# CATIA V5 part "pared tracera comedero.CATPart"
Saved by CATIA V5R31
Part number: pared tracera comedero
Bounding box of the stored display mesh (mm): x -124.2 to 124.2, y -170.5 to 29.5, z 0 to 3.3
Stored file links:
  C:\Users\189361\Desktop\pared tracera comedero.CATPart
  C:\Users\189361\Desktop\pared frontal comedero.CATPart
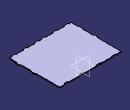
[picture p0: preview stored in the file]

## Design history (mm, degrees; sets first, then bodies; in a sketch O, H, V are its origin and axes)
Set1 "sketch"
  Sketch1 on xy-plane, origin (0, 0, 0), H (1, 0, 0), V (0, 1, 0)
    point P1 (0, 29.5)
    line L1 (0, 29.5) -> (-120.9, 29.5)
    point P2 (-120.9, 29.5)
    line L2 (-120.9, 29.5) -> (-120.9, -64.3)
    point P3 (-120.9, -167.2)
    point P4 (-95.65, -170.5)
    line L3 (-95.65, -170.5) -> (-95.65, -167.2)
    point P5 (-95.65, -167.2)
    line L4 (-95.65, -167.2) -> (-66.45, -167.2)
    point P6 (-66.45, -167.2)
    line L5 (-66.45, -167.2) -> (-66.45, -170.5)
    point P7 (-66.45, -170.5)
    line L6 (-66.45, -170.5) -> (-50.65, -170.5)
    point P8 (-50.65, -170.5)
    line L7 (-50.65, -170.5) -> (-50.65, -167.2)
    point P9 (-50.65, -167.2)
    line L8 (-50.65, -167.2) -> (-21.45, -167.2)
    point P10 (-21.45, -167.2)
    line L9 (-21.45, -167.2) -> (-21.45, -170.5)
    point P11 (-21.45, -170.5)
    line L10 (-21.45, -170.5) -> (-5.65, -170.5)
    point P12 (-5.65, -170.5)
    line L11 (-5.65, -170.5) -> (-5.65, -167.2)
    point P13 (-5.65, -167.2)
    line L12 (-5.65, -167.2) -> (0, -167.2)
    point P14 (0, -167.2)
    line L13 (-120.9, -167.2) -> (-111.45, -167.2)
    point P15 (-111.45, -167.2)
    line L14 (-111.45, -167.2) -> (-111.45, -170.5)
    point P16 (-111.45, -170.5)
    line L15 (-111.45, -170.5) -> (-95.65, -170.5)
    point P17 (-124.2, -140.1)
    line L16 (-124.2, -140.1) -> (-124.2, -124.3)
    point P18 (-124.2, -124.3)
    line L17 (-124.2, -124.3) -> (-120.9, -124.3)
    point P19 (-120.9, -124.3)
    line L18 (-124.2, -140.1) -> (-120.9, -140.1)
    point P20 (-120.9, -140.1)
    line L19 (-120.9, -140.1) -> (-120.9, -167.2)
    construction line L20 (-137.9355, -132.2) -> (-107.3097, -132.2)
    point P22 (-107.3097, -132.2)
    point P23 (120.9, 29.5)
    point P24 (120.9, -167.2)
    point P25 (95.65, -170.5)
    point P26 (95.65, -167.2)
    point P27 (66.45, -167.2)
    point P28 (66.45, -170.5)
    point P29 (50.65, -170.5)
    point P30 (50.65, -167.2)
    point P31 (21.45, -167.2)
    point P32 (21.45, -170.5)
    point P33 (5.65, -170.5)
    point P34 (5.65, -167.2)
    point P35 (111.45, -167.2)
    point P36 (111.45, -170.5)
    point P37 (124.2, -140.1)
    point P38 (124.2, -124.3)
    point P39 (120.9, -124.3)
    point P40 (120.9, -140.1)
    point P41 (107.3097, -132.2)
    line L21 (120.9, 29.5) -> (120.9, -64.3)
    line L22 (95.65, -170.5) -> (95.65, -167.2)
    line L23 (95.65, -167.2) -> (66.45, -167.2)
    line L24 (66.45, -167.2) -> (66.45, -170.5)
    line L25 (66.45, -170.5) -> (50.65, -170.5)
    line L26 (50.65, -170.5) -> (50.65, -167.2)
    line L27 (50.65, -167.2) -> (21.45, -167.2)
    line L28 (21.45, -167.2) -> (21.45, -170.5)
    line L29 (21.45, -170.5) -> (5.65, -170.5)
    line L30 (5.65, -170.5) -> (5.65, -167.2)
    line L31 (120.9, -167.2) -> (111.45, -167.2)
    line L32 (111.45, -167.2) -> (111.45, -170.5)
    line L33 (111.45, -170.5) -> (95.65, -170.5)
    line L34 (124.2, -140.1) -> (124.2, -124.3)
    line L35 (124.2, -124.3) -> (120.9, -124.3)
    line L36 (124.2, -140.1) -> (120.9, -140.1)
    line L37 (120.9, -140.1) -> (120.9, -167.2)
    point P42 (0, -167.2)
    line L38 (5.65, -167.2) -> (0, -167.2)
    point P43 (0, 29.5)
    line L39 (0, 29.5) -> (120.9, 29.5)
    construction line L40 (0, -9.1884) -> (-6.05, -9.1884)
    point P44 (0, -9.1884)
    point P45 (-6.05, -9.1884)
    construction line L41 (-6.05, -9.1884) -> (-21.05, -9.1884)
    point P46 (-21.05, -9.1884)
    construction line L42 (-21.05, -9.1884) -> (-51.05, -9.1884)
    construction line L43 (-51.05, -9.1884) -> (-66.05, -9.1884)
    point P48 (-66.05, -9.1884)
    construction line L44 (-66.05, -9.1884) -> (-96.05, -9.1884)
    construction line L45 (-96.05, -9.1884) -> (-111.05, -9.1884)
    point P50 (-111.05, -9.1884)
    axis line L46 (-142.1875, -102.2) -> (-83.2579, -102.2)
    point P53 (-120.9, -64.3)
    point P54 (-124.2, -64.3)
    line L47 (-124.2, -64.3) -> (-120.9, -64.3)
    point P55 (-124.2, -80.1)
    line L48 (-124.2, -64.3) -> (-124.2, -80.1)
    point P56 (-120.9, -80.1)
    line L49 (-124.2, -80.1) -> (-120.9, -80.1)
    line L50 (-120.9, -80.1) -> (-120.9, -124.3)
    point P57 (120.9, -64.3)
    point P58 (124.2, -64.3)
    point P59 (124.2, -80.1)
    point P60 (120.9, -80.1)
    line L51 (124.2, -64.3) -> (120.9, -64.3)
    line L52 (124.2, -64.3) -> (124.2, -80.1)
    line L53 (124.2, -80.1) -> (120.9, -80.1)
    line L54 (120.9, -80.1) -> (120.9, -124.3)
    length L4 = 29.2
    length L3 = 3.3
    distance V L2 = 120.9
    distance H L1 = 29.5
    distance P2 P3 = 196.7
    length L17 = 3.3
    distance L20 L13 = 35
    distance L20 L17 = 7.9
    distance L20 L18 = 7.9
    length L8 = 29.2
    length L40 = 6.05
    length L41 = 15
    length L42 = 30
    length L43 = 15
    length L44 = 30
    length L45 = 15
    distance P45 L11 = 0.4
    distance L9 P46 = 0.4
    distance L5 P48 = 0.4
    distance L14 P50 = 0.4
    distance L11 V = 5.65 (reference)
    distance L20 L46 = 30
    horizontal: L1 H, L4 H, L6 H, L8 H, L10 H, L12 H, L13 H, L15 H, L17 H, L18 H, L20 H, L40 H, L41 H, L42 H, L43 H, L44 H, L45 H, L46 H
    vertical: L2 V, L3 V, L5 V, L7 V, L9 V, L11 V, L14 V, L16 V, L19 V, L50 V
    coincidence: P9 L4, P13 L4, P14 V, P1 V, P3 L4, P16 L6, P20 L2, L2 L19, P1 P43, P14 P42, P44 V, L2 L50, L21 L54
    equal size: L3 L5, L5 L7, L7 L9, L9 L11
    symmetry: P2 P23 V, P3 P24 V, P4 P25 V, P5 P26 V, P6 P27 V, P7 P28 V, P8 P29 V, P9 P30 V, P10 P31 V, P11 P32 V, P12 P33 V, P13 P34 V, P15 P35 V, P16 P36 V, P17 P37 V, P18 P38 V, P19 P39 V, P20 P40 V, P22 P41 V, L2 L21 V, L3 L22 V, L4 L23 V, L5 L24 V, L6 L25 V, L7 L26 V, L8 L27 V, L9 L28 V, L10 L29 V, L11 L30 V, L13 L31 V, L14 L32 V, L15 L33 V, L16 L34 V, L17 L35 V, L18 L36 V, L19 L37 V, P14 P42 V, L12 L38 V, P1 P43 V, L1 L39 V, P20 P53 L46, P17 P54 L46, L18 L47 L46, P18 P55 L46, L16 L48 L46, P19 P56 L46, L17 L49 L46, P53 P57 V, P54 P58 V, P55 P59 V, P56 P60 V, L47 L51 V, L48 L52 V, L49 L53 V
  Sketch2 on end face of Pad1, origin (0, 0, 3.3), H (1, 0, 0), V (0, 1, 0)
    point P1 (-100.9, 29.5)
    line L1 (-100.9, 29.5) -> (-85.9, 29.5)
    point P2 (-85.9, 29.5)
    line L2 (-85.9, 29.5) -> (-85.9, 26.2)
    point P3 (-85.9, 26.2)
    line L3 (-85.9, 26.2) -> (-100.9, 26.2)
    point P4 (-100.9, 26.2)
    line L4 (-100.9, 26.2) -> (-100.9, 29.5)
    construction line L5 (-93.4, 56.3208) -> (-93.4, 99.4571)
    reference projected line E1 (-120.9, 29.5) -> (-120.9, -64.3) from edge [face of Pad1 from Sketch1.L2 | end face of Pad1]
    axis line L6 (-63.4, 68.297) -> (-63.4, 98.7025)
    point P9 (-25.9, 29.5)
    point P10 (-40.9, 29.5)
    point P11 (-40.9, 26.2)
    point P12 (-25.9, 26.2)
    line L7 (-25.9, 29.5) -> (-40.9, 29.5)
    line L8 (-40.9, 29.5) -> (-40.9, 26.2)
    line L9 (-40.9, 26.2) -> (-25.9, 26.2)
    line L10 (-25.9, 26.2) -> (-25.9, 29.5)
    point P13 (100.9, 29.5)
    point P14 (85.9, 29.5)
    point P15 (85.9, 26.2)
    point P16 (100.9, 26.2)
    point P17 (25.9, 29.5)
    point P18 (40.9, 29.5)
    point P19 (40.9, 26.2)
    point P20 (25.9, 26.2)
    line L11 (100.9, 29.5) -> (85.9, 29.5)
    line L12 (85.9, 29.5) -> (85.9, 26.2)
    line L13 (85.9, 26.2) -> (100.9, 26.2)
    line L14 (100.9, 26.2) -> (100.9, 29.5)
    line L15 (25.9, 29.5) -> (40.9, 29.5)
    line L16 (40.9, 29.5) -> (40.9, 26.2)
    line L17 (40.9, 26.2) -> (25.9, 26.2)
    line L18 (25.9, 26.2) -> (25.9, 29.5)
    reference projected line E2 (0, 29.5) -> (-120.9, 29.5) from edge [face of Pad1 from Sketch1.L1 | end face of Pad1]
    length L1 = 15
    distance L2 L5 = 7.5
    length L4 = 3.3
    distance L4 E1 = 20
    distance L6 L5 = 30
    distance L5 E1 = 27.5 (reference)
    horizontal: L1 H, L3 H
    vertical: L2 V, L4 V, L5 V, L6 V
    symmetry: P1 P9 L6, P2 P10 L6, P3 P11 L6, P4 P12 L6, L1 L7 L6, L2 L8 L6, L3 L9 L6, L4 L10 L6, P1 P13 V, P2 P14 V, P3 P15 V, P4 P16 V, P9 P17 V, P10 P18 V, P11 P19 V, P12 P20 V, L1 L11 V, L2 L12 V, L3 L13 V, L4 L14 V, L7 L15 V, L8 L16 V, L9 L17 V, L10 L18 V
    coincidence: L1 E2
Body1 (main body)
  Pad1: profile Sketch1, direction (0, 0, 1), length 3.3
  Pocket1: profile Sketch2, direction (0, 0, -1), length 3.3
